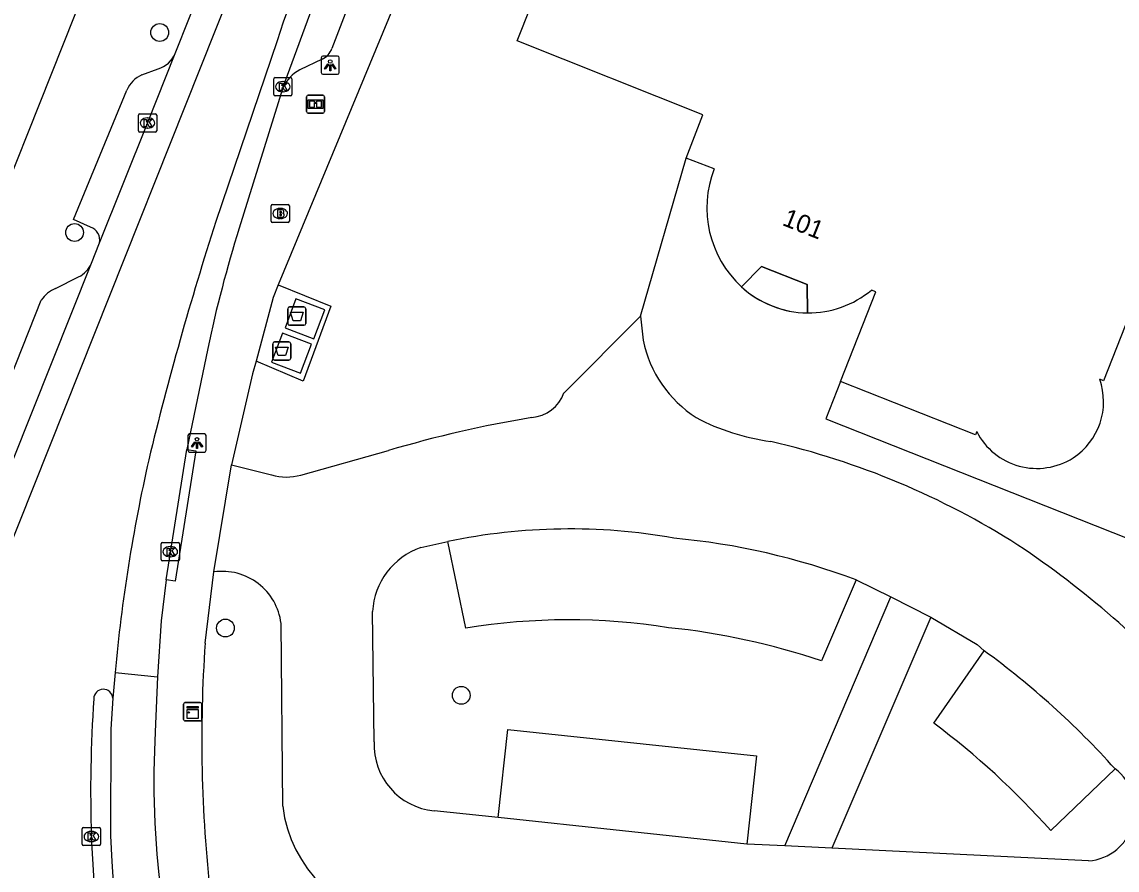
# Model space of a CAD drawing. Extents: x 160026 to 161302, y 384757 to 385701.
# Drawn here: x 160368.3 to 160428.4, y 384834 to 384880.6 of the extents above; entities that cross this region are included whole.
import ezdxf

# ---------------------------------------------------------------- set-up
doc = ezdxf.new("R2010")
doc.units = 0
for name, color, linetype in [('IMGEO_Afval_apart_plaats', 7, 'Continuous'), ('IMGEO_Boom', 7, 'Continuous'), ('IMGEO_Brandkraan', 7, 'Continuous'), ('IMGEO_Fietspad_open', 7, 'Continuous'), ('IMGEO_Informatiebord', 7, 'Continuous'), ('IMGEO_Kast', 7, 'Continuous'), ('IMGEO_Kolk', 7, 'Continuous'), ('IMGEO_Lichtpunt', 7, 'Continuous'), ('IMGEO_Pand', 7, 'Continuous'), ('IMGEO_Pand_nummerreeks', 7, 'Continuous'), ('IMGEO_Pand_overbouw', 7, 'Continuous'), ('IMGEO_Parkeervlak_open', 7, 'Continuous'), ('IMGEO_Rijbaan_lokaal_open', 7, 'Continuous'), ('IMGEO_Voetpad_gesloten', 7, 'Continuous'), ('IMGEO_Voetpad_open', 7, 'Continuous')]:
    doc.layers.add(name, color=color, linetype=linetype)

msp = doc.modelspace()

# ---------------------------------------------------------------- linework, layer by layer
at = {"layer": 'IMGEO_Afval_apart_plaats'}
for p, q in [((160382.887, 384864.007), (160382.887, 384864.807)), ((160382.887, 384864.807), (160382.887, 384864.007)), ((160382.987, 384864.907), (160383.777, 384864.907)), ((160383.777, 384864.907), (160382.987, 384864.907)), ((160383.877, 384864.807), (160383.877, 384864.007)), ((160383.877, 384864.007), (160383.877, 384864.807)), ((160383.777, 384863.907), (160382.987, 384863.907)), ((160382.987, 384863.907), (160383.777, 384863.907)), ((160382.064, 384862.093), (160382.064, 384862.893)), ((160382.064, 384862.893), (160382.064, 384862.093)), ((160382.164, 384862.993), (160382.954, 384862.993)), ((160382.954, 384862.993), (160382.164, 384862.993)), ((160383.054, 384862.893), (160383.054, 384862.093)), ((160383.054, 384862.093), (160383.054, 384862.893)), ((160382.954, 384861.993), (160382.164, 384861.993)), ((160382.164, 384861.993), (160382.954, 384861.993))]:
    msp.add_line(p, q, dxfattribs=at)
for points in [[(160383.03, 384864.621), (160383.734, 384864.621), (160383.585, 384864.151), (160383.179, 384864.151), (160383.03, 384864.621)], [(160382.207, 384862.707), (160382.911, 384862.707), (160382.762, 384862.237), (160382.356, 384862.237), (160382.207, 384862.707)]]:
    msp.add_lwpolyline(points, dxfattribs=at)
for centre, start, end in [((160382.987, 384864.807), 90, 180), ((160382.987, 384864.807), 90, 180), ((160383.777, 384864.807), 0, 90), ((160383.777, 384864.807), 360, 90), ((160382.987, 384864.007), 180, 270), ((160382.987, 384864.007), 180, 270), ((160383.777, 384864.007), 270, 0), ((160383.777, 384864.007), 270, 0), ((160382.164, 384862.893), 90, 180), ((160382.164, 384862.893), 90, 180), ((160382.954, 384862.893), 0, 90), ((160382.954, 384862.893), 360, 90), ((160382.164, 384862.093), 180, 270), ((160382.164, 384862.093), 180, 270), ((160382.954, 384862.093), 270, 0), ((160382.954, 384862.093), 270, 0)]:
    msp.add_arc(centre, 0.1, start, end, dxfattribs=at)
at = {"layer": 'IMGEO_Boom'}
for centre in [(160375.859, 384879.974), (160371.186, 384868.997), (160379.464, 384847.284), (160392.408, 384843.591)]:
    msp.add_circle(centre, 0.489, dxfattribs=at)
at = {"layer": 'IMGEO_Brandkraan'}
for p, q in [((160381.974, 384869.611), (160381.974, 384870.463)), ((160382.049, 384870.537), (160382.901, 384870.537)), ((160382.975, 384870.463), (160382.975, 384869.611)), ((160382.462, 384870.317), (160382.487, 384870.317)), ((160382.901, 384869.537), (160382.049, 384869.537)), ((160382.485, 384869.757), (160382.46, 384869.757))]:
    msp.add_line(p, q, dxfattribs=at)
for points in [[(160381.974, 384869.611), (160381.974, 384870.463)], [(160382.049, 384870.537), (160382.901, 384870.537)], [(160382.975, 384870.463), (160382.975, 384869.611)], [(160382.322, 384870.237), (160382.322, 384869.837), (160382.535, 384869.837)], [(160382.553, 384870.237), (160382.322, 384870.237)], [(160382.501, 384870.156), (160382.447, 384870.156), (160382.447, 384870.08)], [(160382.447, 384870.08), (160382.5, 384870.08)], [(160382.509, 384870.004), (160382.447, 384870.004), (160382.447, 384869.923)], [(160382.447, 384869.923), (160382.509, 384869.923)], [(160382.901, 384869.537), (160382.049, 384869.537)]]:
    msp.add_lwpolyline(points, dxfattribs=at)
for centre, radius, start, end in [((160382.051, 384870.461), 0.0765, 91.55205, 178.44795), ((160382.051, 384870.461), 0.0765, 91.55205, 178.44795), ((160382.899, 384870.461), 0.0765, 1.55205, 88.44795), ((160382.899, 384870.461), 0.0765, 1.55205, 88.44795), ((160382.502, 384870.118), 0.0379, 267.82845, 90.93552), ((160382.51, 384869.963), 0.0404, 269.87594, 90.50774), ((160382.557, 384870.092), 0.145, 59.4692, 91.53667), ((160382.582, 384870.139), 0.0922, 285.51372, 58.15012), ((160382.587, 384869.947), 0.105, 301.31148, 78.98903), ((160382.051, 384869.613), 0.0765, 181.55205, 268.44795), ((160382.051, 384869.613), 0.0765, 181.55205, 268.44795), ((160382.541, 384870.088), 0.251, 268.66757, 293.53466), ((160382.899, 384869.613), 0.0765, 271.55205, 358.44795), ((160382.899, 384869.613), 0.0765, 271.55205, 358.44795)]:
    msp.add_arc(centre, radius, start, end, dxfattribs=at)
for centre, major_axis, ratio, start_param, end_param in [((160382.461, 384870.037), (-0.387, 0.002), 0.722429, 4.712389, 7.853982), ((160382.486, 384870.037), (-0.39, 0.002), 0.717154, 1.570796, 4.712389)]:
    msp.add_ellipse(centre, major_axis=major_axis, ratio=ratio, start_param=start_param, end_param=end_param, dxfattribs=at)
at = {"layer": 'IMGEO_Fietspad_open'}
for points in [[(160375.734, 384844.604), (160375.6, 384841.597), (160375.567, 384840.544)], [(160373.286, 384843.434), (160373.17, 384841.73), (160373.159, 384835.874), (160373.236, 384834.47), (160373.316, 384833.066)]]:
    msp.add_lwpolyline(points, dxfattribs=at)
msp.add_arc((160421.371, 384838.798), 45.837, 177.81663, 189.17371, dxfattribs=at)
at = {"layer": 'IMGEO_Informatiebord'}
for p, q in [((160384.013, 384876.54), (160384.803, 384876.54)), ((160384.803, 384876.54), (160384.013, 384876.54)), ((160383.913, 384875.64), (160383.913, 384876.44)), ((160383.913, 384876.44), (160383.913, 384875.64)), ((160384.903, 384876.44), (160384.903, 384875.64)), ((160384.903, 384875.64), (160384.903, 384876.44)), ((160384.803, 384875.54), (160384.013, 384875.54)), ((160384.013, 384875.54), (160384.803, 384875.54))]:
    msp.add_line(p, q, dxfattribs=at)
for points in [[(160384.014, 384876.272), (160384.802, 384876.272), (160384.802, 384875.808), (160384.014, 384875.808), (160384.014, 384876.272)], [(160384.079, 384876.207), (160384.079, 384875.873), (160384.354, 384875.873), (160384.355, 384876.086), (160384.459, 384876.087), (160384.46, 384875.873), (160384.737, 384875.873), (160384.737, 384876.207), (160384.461, 384876.207), (160384.461, 384876.127), (160384.355, 384876.127), (160384.355, 384876.207), (160384.079, 384876.207)]]:
    msp.add_lwpolyline(points, dxfattribs=at)
for centre, start, end in [((160384.013, 384876.44), 90, 180), ((160384.013, 384876.44), 90, 180), ((160384.803, 384876.44), 0, 90), ((160384.803, 384876.44), 360, 90), ((160384.013, 384875.64), 180, 270), ((160384.013, 384875.64), 180, 270), ((160384.803, 384875.64), 270, 0), ((160384.803, 384875.64), 270, 0)]:
    msp.add_arc(centre, 0.1, start, end, dxfattribs=at)
at = {"layer": 'IMGEO_Kast'}
for p, q in [((160377.169, 384842.265), (160377.169, 384843.106)), ((160377.169, 384843.106), (160377.169, 384842.265)), ((160377.244, 384843.19), (160378.085, 384843.19)), ((160378.085, 384843.19), (160377.244, 384843.19)), ((160378.169, 384843.115), (160378.169, 384842.274)), ((160378.169, 384842.274), (160378.169, 384843.115)), ((160378.094, 384842.19), (160377.253, 384842.19)), ((160377.253, 384842.19), (160378.094, 384842.19))]:
    msp.add_line(p, q, dxfattribs=at)
for points in [[(160377.364, 384842.98), (160377.964, 384842.98), (160377.964, 384842.895), (160377.364, 384842.895), (160377.364, 384842.98)], [(160377.364, 384842.805), (160377.964, 384842.805), (160377.964, 384842.316), (160377.364, 384842.316), (160377.364, 384842.805)]]:
    msp.add_lwpolyline(points, dxfattribs=at)
msp.add_circle((160377.448, 384842.654), 0.0377, dxfattribs=at)
for centre, start, end in [((160377.247, 384843.112), 92.4484, 184.28452), ((160377.247, 384843.112), 92.4484, 184.28452), ((160378.091, 384843.112), 2.4484, 94.28452), ((160378.091, 384843.112), 2.4484, 94.28452), ((160377.247, 384842.268), 182.4484, 274.28452), ((160377.247, 384842.268), 182.4484, 274.28452), ((160378.091, 384842.268), 272.4484, 4.28452), ((160378.091, 384842.268), 272.4484, 4.28452)]:
    msp.add_arc(centre, 0.0779, start, end, dxfattribs=at)
at = {"layer": 'IMGEO_Kolk'}
for p, q in [((160382.117, 384876.571), (160382.117, 384877.423)), ((160382.192, 384877.497), (160383.044, 384877.497)), ((160382.605, 384877.277), (160382.63, 384877.277)), ((160383.118, 384877.423), (160383.118, 384876.571)), ((160383.044, 384876.497), (160382.192, 384876.497)), ((160382.628, 384876.717), (160382.603, 384876.717)), ((160374.691, 384874.579), (160374.691, 384875.431)), ((160374.766, 384875.505), (160375.618, 384875.505)), ((160375.179, 384875.285), (160375.204, 384875.285)), ((160375.692, 384875.431), (160375.692, 384874.579)), ((160375.202, 384874.725), (160375.177, 384874.725)), ((160375.618, 384874.505), (160374.766, 384874.505)), ((160375.938, 384851.049), (160375.938, 384851.901)), ((160376.013, 384851.975), (160376.865, 384851.975)), ((160376.939, 384851.901), (160376.939, 384851.049)), ((160376.426, 384851.755), (160376.451, 384851.755)), ((160376.865, 384850.975), (160376.013, 384850.975)), ((160376.449, 384851.195), (160376.424, 384851.195)), ((160371.606, 384835.415), (160371.606, 384836.267)), ((160371.681, 384836.341), (160372.533, 384836.341)), ((160372.607, 384836.267), (160372.607, 384835.415)), ((160372.094, 384836.121), (160372.119, 384836.121)), ((160372.533, 384835.341), (160371.681, 384835.341)), ((160372.117, 384835.561), (160372.092, 384835.561))]:
    msp.add_line(p, q, dxfattribs=at)
for points in [[(160382.117, 384876.571), (160382.117, 384877.423)], [(160382.192, 384877.497), (160383.044, 384877.497)], [(160382.438, 384877.197), (160382.561, 384877.197), (160382.561, 384877.046), (160382.691, 384877.197), (160382.855, 384877.197), (160382.709, 384877.046), (160382.862, 384876.797), (160382.71, 384876.797), (160382.625, 384876.961), (160382.561, 384876.894), (160382.561, 384876.797), (160382.438, 384876.797), (160382.438, 384877.197)], [(160383.118, 384877.423), (160383.118, 384876.571)], [(160383.044, 384876.497), (160382.192, 384876.497)], [(160374.691, 384874.579), (160374.691, 384875.431)], [(160374.766, 384875.505), (160375.618, 384875.505)], [(160375.692, 384875.431), (160375.692, 384874.579)], [(160375.012, 384875.205), (160375.135, 384875.205), (160375.135, 384875.054), (160375.265, 384875.205), (160375.429, 384875.205), (160375.283, 384875.054), (160375.436, 384874.805), (160375.284, 384874.805), (160375.199, 384874.969), (160375.135, 384874.902), (160375.135, 384874.805), (160375.012, 384874.805), (160375.012, 384875.205)], [(160375.618, 384874.505), (160374.766, 384874.505)], [(160375.938, 384851.049), (160375.938, 384851.901)], [(160376.013, 384851.975), (160376.865, 384851.975)], [(160376.939, 384851.901), (160376.939, 384851.049)], [(160376.259, 384851.675), (160376.382, 384851.675), (160376.382, 384851.524), (160376.512, 384851.675), (160376.676, 384851.675), (160376.53, 384851.524), (160376.683, 384851.275), (160376.531, 384851.275), (160376.446, 384851.439), (160376.382, 384851.372), (160376.382, 384851.275), (160376.259, 384851.275), (160376.259, 384851.675)], [(160376.865, 384850.975), (160376.013, 384850.975)], [(160371.606, 384835.415), (160371.606, 384836.267)], [(160371.681, 384836.341), (160372.533, 384836.341)], [(160372.607, 384836.267), (160372.607, 384835.415)], [(160371.927, 384836.041), (160372.05, 384836.041), (160372.05, 384835.89), (160372.18, 384836.041), (160372.344, 384836.041), (160372.198, 384835.89), (160372.351, 384835.641), (160372.199, 384835.641), (160372.114, 384835.805), (160372.05, 384835.738), (160372.05, 384835.641), (160371.927, 384835.641), (160371.927, 384836.041)], [(160372.533, 384835.341), (160371.681, 384835.341)]]:
    msp.add_lwpolyline(points, dxfattribs=at)
for centre, start, end in [((160382.194, 384877.421), 91.55205, 178.44795), ((160382.194, 384877.421), 91.55205, 178.44795), ((160383.042, 384877.421), 1.55205, 88.44795), ((160383.042, 384877.421), 1.55205, 88.44795), ((160382.194, 384876.573), 181.55205, 268.44795), ((160382.194, 384876.573), 181.55205, 268.44795), ((160383.042, 384876.573), 271.55205, 358.44795), ((160383.042, 384876.573), 271.55205, 358.44795), ((160374.768, 384875.429), 91.55205, 178.44795), ((160374.768, 384875.429), 91.55205, 178.44795), ((160375.616, 384875.429), 1.55205, 88.44795), ((160375.616, 384875.429), 1.55205, 88.44795), ((160374.768, 384874.581), 181.55205, 268.44795), ((160374.768, 384874.581), 181.55205, 268.44795), ((160375.616, 384874.581), 271.55205, 358.44795), ((160375.616, 384874.581), 271.55205, 358.44795), ((160376.015, 384851.899), 91.55205, 178.44795), ((160376.015, 384851.899), 91.55205, 178.44795), ((160376.863, 384851.899), 1.55205, 88.44795), ((160376.863, 384851.899), 1.55205, 88.44795), ((160376.015, 384851.051), 181.55205, 268.44795), ((160376.015, 384851.051), 181.55205, 268.44795), ((160376.863, 384851.051), 271.55205, 358.44795), ((160376.863, 384851.051), 271.55205, 358.44795), ((160371.683, 384836.265), 91.55205, 178.44795), ((160371.683, 384836.265), 91.55205, 178.44795), ((160372.531, 384836.265), 1.55205, 88.44795), ((160372.531, 384836.265), 1.55205, 88.44795), ((160371.683, 384835.417), 181.55205, 268.44795), ((160371.683, 384835.417), 181.55205, 268.44795), ((160372.531, 384835.417), 271.55205, 358.44795), ((160372.531, 384835.417), 271.55205, 358.44795)]:
    msp.add_arc(centre, 0.0765, start, end, dxfattribs=at)
for centre, major_axis, ratio, start_param, end_param in [((160382.604, 384876.997), (-0.387, 0.002), 0.722429, 4.712389, 7.853982), ((160382.629, 384876.997), (-0.39, 0.002), 0.717154, 1.570796, 4.712389), ((160375.178, 384875.005), (-0.387, 0.002), 0.722429, 4.712389, 7.853982), ((160375.203, 384875.005), (-0.39, 0.002), 0.717154, 1.570796, 4.712389), ((160376.425, 384851.475), (-0.387, 0.002), 0.722429, 4.712389, 7.853982), ((160376.45, 384851.475), (-0.39, 0.002), 0.717154, 1.570796, 4.712389), ((160372.093, 384835.841), (-0.387, 0.002), 0.722429, 4.712389, 7.853982), ((160372.118, 384835.841), (-0.39, 0.002), 0.717154, 1.570796, 4.712389)]:
    msp.add_ellipse(centre, major_axis=major_axis, ratio=ratio, start_param=start_param, end_param=end_param, dxfattribs=at)
at = {"layer": 'IMGEO_Lichtpunt'}
for p, q in [((160384.72, 384878.584), (160384.72, 384877.777)), ((160384.72, 384878.584), (160384.72, 384877.777)), ((160385.622, 384878.679), (160384.814, 384878.679)), ((160385.622, 384878.679), (160384.814, 384878.679)), ((160385.716, 384877.777), (160385.716, 384878.584)), ((160385.716, 384877.777), (160385.716, 384878.584)), ((160384.814, 384877.683), (160385.622, 384877.683)), ((160384.814, 384877.683), (160385.622, 384877.683)), ((160377.407, 384857.848), (160377.407, 384857.041)), ((160377.407, 384857.848), (160377.407, 384857.041)), ((160378.309, 384857.943), (160377.501, 384857.943)), ((160378.309, 384857.943), (160377.501, 384857.943)), ((160378.403, 384857.041), (160378.403, 384857.848)), ((160378.403, 384857.041), (160378.403, 384857.848)), ((160377.501, 384856.947), (160378.309, 384856.947)), ((160377.501, 384856.947), (160378.309, 384856.947))]:
    msp.add_line(p, q, dxfattribs=at)
for points in [[(160385.094, 384878.248), (160385.133, 384878.22), (160384.945, 384877.958), (160384.907, 384877.985), (160385.094, 384878.248)], [(160385.196, 384878.2), (160385.243, 384878.2), (160385.243, 384877.878), (160385.196, 384877.878), (160385.196, 384878.2)], [(160385.306, 384878.22), (160385.344, 384878.247), (160385.531, 384877.985), (160385.492, 384877.957), (160385.306, 384878.22)], [(160377.781, 384857.512), (160377.82, 384857.484), (160377.632, 384857.222), (160377.594, 384857.249), (160377.781, 384857.512)], [(160377.883, 384857.464), (160377.93, 384857.464), (160377.93, 384857.142), (160377.883, 384857.142), (160377.883, 384857.464)], [(160377.993, 384857.484), (160378.031, 384857.511), (160378.218, 384857.249), (160378.179, 384857.221), (160377.993, 384857.484)]]:
    msp.add_lwpolyline(points, dxfattribs=at)
for centre in [(160385.219, 384878.382), (160377.906, 384857.646)]:
    msp.add_circle(centre, 0.0994, dxfattribs=at)
for centre, start, end in [((160384.814, 384878.584), 90, 180), ((160384.814, 384878.584), 90, 180), ((160385.622, 384878.584), 0, 90), ((160385.622, 384878.584), 0, 90), ((160384.814, 384877.777), 180, 270), ((160384.814, 384877.777), 180, 270), ((160385.622, 384877.777), 270, 0), ((160385.622, 384877.777), 270, 360), ((160377.501, 384857.848), 90, 180), ((160377.501, 384857.848), 90, 180), ((160378.309, 384857.848), 0, 90), ((160378.309, 384857.848), 0, 90), ((160377.501, 384857.041), 180, 270), ((160377.501, 384857.041), 180, 270), ((160378.309, 384857.041), 270, 0), ((160378.309, 384857.041), 270, 360)]:
    msp.add_arc(centre, 0.0946, start, end, dxfattribs=at)
at = {"layer": 'IMGEO_Pand'}
for points in [[(160412.642, 384908.106), (160412.733, 384908.325), (160420.167, 384905.387), (160417.549, 384898.775), (160416.515, 384896.163), (160414.208, 384890.335), (160435.946, 384881.652), (160429.921, 384866.554), (160428.854, 384863.881), (160427.65, 384860.863), (160427.449, 384860.941)], [(160404.751, 384873.083), (160405.674, 384875.447), (160395.472, 384879.515), (160405.765, 384905.361), (160405.969, 384905.287)], [(160406.29, 384872.484), (160404.751, 384873.083)], [(160407.793, 384866.012), (160408.883, 384867.138), (160411.388, 384866.147), (160411.403, 384864.584)], [(160413.22, 384860.816), (160415.169, 384865.732), (160414.924, 384865.839)], [(160420.698, 384858.069), (160420.631, 384857.884), (160413.22, 384860.816)]]:
    msp.add_lwpolyline(points, dxfattribs=at)
for centre, radius, start, end in [((160411.763, 384870.344), 5.876, 158.64723, 227.50101), ((160411.457, 384869.999), 5.415, 269.42841, 309.80706), ((160423.976, 384859.711), 3.684, 303.11493, 19.4981), ((160423.998, 384859.749), 3.703, 206.97473, 302.51504)]:
    msp.add_arc(centre, radius, start, end, dxfattribs=at)
at = {"layer": 'IMGEO_Pand_overbouw'}
msp.add_lwpolyline([(160407.793, 384866.012), (160408.173, 384865.693), (160408.581, 384865.411), (160409.013, 384865.167), (160409.466, 384864.963), (160409.935, 384864.802), (160410.417, 384864.685), (160410.908, 384864.612), (160411.403, 384864.584), (160411.388, 384866.147), (160408.883, 384867.138)], close=True, dxfattribs=at)
at = {"layer": 'IMGEO_Parkeervlak_open'}
for points in [[(160392.657, 384847.286), (160391.679, 384852.03)], [(160414.084, 384849.927), (160412.174, 384845.486)], [(160418.343, 384842.057), (160421.11, 384846.038)], [(160394.442, 384836.887), (160394.967, 384841.713), (160408.619, 384840.268), (160408.089, 384835.428)], [(160428.289, 384839.56), (160424.759, 384836.167)]]:
    msp.add_lwpolyline(points, dxfattribs=at)
for centre, radius, start, end in [((160398.28, 384812.464), 35.273, 81.01271, 99.17256), ((160399.793, 384808.628), 38.882, 71.4316, 84.09901), ((160392.957, 384807.964), 42.506, 41.56721, 53.32784)]:
    msp.add_arc(centre, radius, start, end, dxfattribs=at)
at = {"layer": 'IMGEO_Rijbaan_lokaal_open'}
for points in [[(160382.619, 384876.93), (160386.339, 384887.1), (160431.47, 385000), (160434.346, 385007.194)], [(160366.607, 384848.835), (160367.328, 384850.977), (160383.069, 384890.556)], [(160376.702, 384878.824), (160379.059, 384884.775)], [(160382.302, 384879.524), (160378.944, 384869.606)], [(160372.559, 384868.423), (160375.189, 384875.005), (160376.702, 384878.824)], [(160382.619, 384876.93), (160380.216, 384869.227)], [(160372.113, 384867.309), (160372.559, 384868.423)], [(160366.266, 384852.652), (160367.753, 384856.397), (160372.113, 384867.309)], [(160398.045, 384860.186), (160402.246, 384864.412)], [(160402.246, 384864.412), (160402.388, 384863.084)], [(160378.495, 384862.629), (160377.347, 384857.092)], [(160376.205, 384849.926), (160377.347, 384857.092)], [(160383.607, 384855.681), (160388.414, 384857.028)], [(160378.835, 384850.364), (160379.807, 384856.25)], [(160379.807, 384856.25), (160382, 384855.691)], [(160390.185, 384851.698), (160391.679, 384852.03)], [(160376.205, 384849.926), (160375.946, 384847.68), (160375.734, 384844.604)], [(160414.084, 384849.927), (160415.982, 384849.007)], [(160415.982, 384849.007), (160418.174, 384847.891)], [(160387.624, 384841.042), (160387.541, 384848.194)], [(160418.174, 384847.891), (160420.731, 384846.384), (160421.11, 384846.038)], [(160382.609, 384837.5), (160382.52, 384847.543)], [(160373.406, 384844.85), (160373.286, 384843.434)], [(160373.406, 384844.85), (160375.734, 384844.604)], [(160394.442, 384836.887), (160390.92, 384837.245)], [(160408.089, 384835.428), (160394.442, 384836.887)], [(160372.26, 384833.372), (160372.106, 384835.844)], [(160410.162, 384835.325), (160408.089, 384835.428)], [(160412.751, 384835.197), (160410.162, 384835.325)], [(160426.837, 384834.499), (160412.751, 384835.197)]]:
    msp.add_lwpolyline(points, dxfattribs=at)
for centre, radius, start, end in [((160508.642, 384837.412), 133.174, 157.89426, 161.56582), ((160551.654, 384813.862), 181.483, 162.11192, 166.40591), ((160448.74, 384847.83), 71.787, 162.65872, 168.10306), ((160408.887, 384864.422), 6.636, 191.63195, 237.31521), ((160396.086, 384860.925), 2.094, 275.34563, 339.34442), ((160407.07, 384794.016), 65.716, 99.44915, 106.49221), ((160410.98, 384869.545), 12.12, 242.07136, 262.46879), ((160399.592, 384815.12), 43.527, 57.52478, 76.9881), ((160464.507, 384836.394), 91.492, 167.29373, 174.69698), ((160382.821, 384858.436), 2.865, 253.3535, 285.93343), ((160398.364, 384820.213), 32.512, 79.87078, 101.86603), ((160400.53, 384813.733), 38.648, 69.47022, 84.72721), ((160394.597, 384809.319), 51.115, 41.55672, 56.29261), ((160391.476, 384847.974), 3.942, 109.12631, 176.79975), ((160379.288, 384847.139), 3.257, 7.12696, 98.00233), ((160394.023, 384808.803), 46.044, 41.91098, 53.96573), ((160372.764, 384843.403), 0.523, 3.36004, 180.47652), ((160447.629, 384838.273), 75.562, 176.11031, 181.84228), ((160391.281, 384840.888), 3.66, 177.58297, 264.33651), ((160426.594, 384837.307), 2.819, 274.93533, 53.04832), ((160389.711, 384838.346), 7.152, 186.78915, 266.08747)]:
    msp.add_arc(centre, radius, start, end, dxfattribs=at)
at = {"layer": 'IMGEO_Voetpad_gesloten'}
for points in [[(160383.338, 384865.348), (160382.736, 384863.761), (160384.326, 384863.158), (160384.928, 384864.745), (160383.338, 384865.348)], [(160382.604, 384863.467), (160382.002, 384861.88), (160383.591, 384861.277), (160384.193, 384862.864), (160382.604, 384863.467)]]:
    msp.add_lwpolyline(points, dxfattribs=at)
at = {"layer": 'IMGEO_Voetpad_open'}
for points in [[(160404.882, 384922.015), (160403.358, 384918.197), (160394.783, 384896.085), (160382.365, 384866.119)], [(160399.64, 384915.454), (160389.215, 384889.291), (160385.303, 384879.087)], [(160372.439, 384884.099), (160364.181, 384863.317)], [(160384.779, 384878.517), (160383.55, 384877.928)], [(160374.882, 384877.654), (160375.773, 384877.973)], [(160372.055, 384869.294), (160371.135, 384869.71), (160374.057, 384876.809)], [(160402.246, 384864.412), (160404.751, 384873.083)], [(160370.141, 384865.93), (160371.41, 384866.556)], [(160382.365, 384866.119), (160385.246, 384864.955), (160383.723, 384860.834), (160381.146, 384861.936)], [(160382.365, 384866.119), (160382.078, 384865.427), (160381.146, 384861.936)], [(160366.282, 384857.559), (160369.36, 384865.279)], [(160381.146, 384861.936), (160380.957, 384861.23), (160379.807, 384856.25)], [(160413.22, 384860.816), (160412.421, 384858.769), (160430.011, 384851.804), (160430.357, 384851.667), (160435.115, 384849.756), (160434.302, 384847.755), (160440.014, 384845.438), (160440.981, 384847.843)], [(160377.347, 384857.092), (160377.84, 384857.014), (160376.7, 384849.862), (160376.205, 384849.926)], [(160378.35, 384846.454), (160378.835, 384850.364)], [(160410.162, 384835.325), (160415.982, 384849.007)], [(160418.174, 384847.891), (160412.751, 384835.197)]]:
    msp.add_lwpolyline(points, dxfattribs=at)
for centre, radius, start, end in [((160384.374, 384879.415), 0.985, 294.27057, 340.54489), ((160375.329, 384879.39), 1.485, 287.38691, 337.59487), ((160384.46, 384876.145), 2.002, 117.05618, 156.92233), ((160375.559, 384876.168), 1.633, 114.48971, 156.88257), ((160371.805, 384868.568), 0.768, 349.10547, 71.00576), ((160370.63, 384867.988), 1.631, 298.55591, 335.37769), ((160370.83, 384864.31), 1.761, 113.03017, 146.5954), ((160411.456, 384869.996), 5.412, 227.40024, 269.43544), ((160454.392, 384841.183), 76.224, 176.03453, 186.49009)]:
    msp.add_arc(centre, radius, start, end, dxfattribs=at)

# ---------------------------------------------------------------- texts
at = {"layer": 'IMGEO_Pand_nummerreeks'}
msp.add_text('101', height=1, rotation=338.41668, dxfattribs=at).set_placement((160409.971, 384869.418))

doc.saveas('drawing.dxf')
